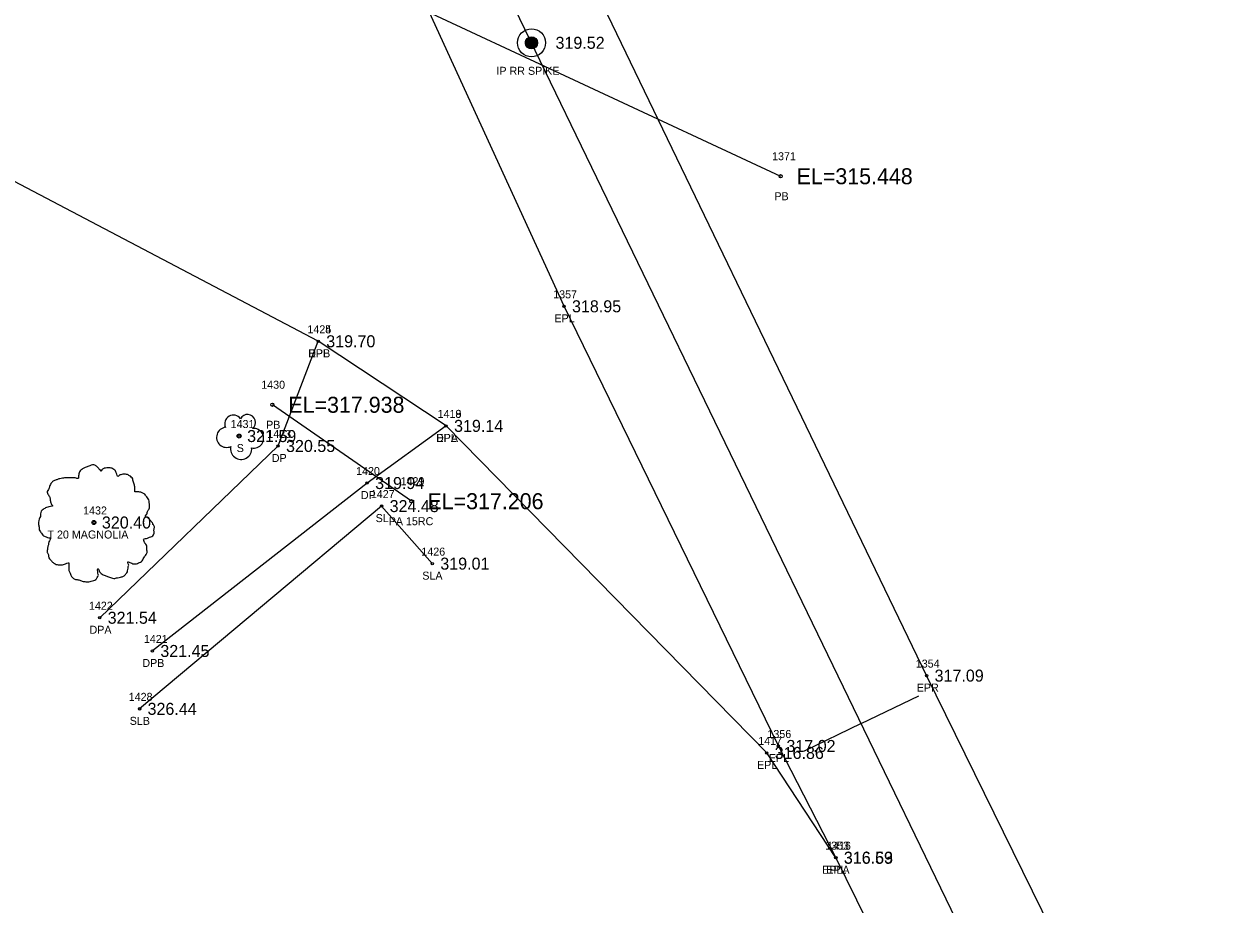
# Model space of a CAD drawing. Extents: x 1865045 to 1867370, y 910391 to 914218.
# Drawn here: x 1865995.4 to 1866144.3, y 911645.7 to 911755.7 of the extents above; entities that cross this region are included whole.
import ezdxf

# ---------------------------------------------------------------- set-up
doc = ezdxf.new("R2010")
doc.units = 0
for name, color, linetype in [('RD_EX_DR_Pipe', 7, 'Continuous'), ('RD_EX_DR_Pipe_txCode', 7, 'Continuous'), ('RD_EX_Driveway', 7, 'Continuous'), ('RD_EX_Driveway_txCode', 7, 'Continuous'), ('RD_EX_DV_Prop_txCode', 7, 'Continuous'), ('RD_EX_DV_PropPin', 7, 'Continuous'), ('RD_EX_Road', 7, 'Continuous'), ('RD_EX_Road_txCode', 7, 'Continuous'), ('RD_EX_TX_Driveway_ELEV', 7, 'Continuous'), ('RD_EX_TX_DV_Prop_ELEV', 7, 'Continuous'), ('RD_EX_TX_Road_ELEV', 7, 'Continuous'), ('RD_EX_TX_VEG_ELEV', 7, 'Continuous'), ('RD_EX_VEG', 7, 'Continuous'), ('RD_EX_VEG_txCode', 7, 'Continuous'), ('RD_HC_Cl', 7, 'Continuous'), ('RD_HC_Data_Tic', 7, 'Continuous'), ('RD_SMD_Locator', 7, 'Continuous'), ('RD_TX_Pipe_ElevEX', 7, 'Continuous')]:
    doc.layers.add(name, color=color, linetype=linetype)

msp = doc.modelspace()

# ---------------------------------------------------------------- linework, layer by layer
at = {"layer": 'RD_EX_DR_Pipe'}
for p, q in [((1866017.31, 911770.52), (1866089.93, 911736.64)), ((1866043.81, 911696.04), (1866026.44, 911708.09))]:
    msp.add_line(p, q, dxfattribs=at)
at = {"layer": 'RD_EX_Driveway'}
for points in [[(1866004.87, 911681.48), (1866027.15, 911702.94), (1866032.17, 911716.02)], [(1866048.14, 911705.45), (1866038.28, 911698.31), (1866011.45, 911677.33)]]:
    msp.add_lwpolyline(points, dxfattribs=at)
at = {"layer": 'RD_EX_DV_PropPin'}
for p, q in [((1866058.08, 911753.12), (1866058.08, 911753.51)), ((1866058.11, 911753.01), (1866058.11, 911753.61)), ((1866058.15, 911752.94), (1866058.15, 911753.68)), ((1866058.18, 911752.89), (1866058.18, 911753.74)), ((1866058.22, 911752.84), (1866058.22, 911753.79)), ((1866058.25, 911752.8), (1866058.25, 911753.83)), ((1866058.29, 911752.76), (1866058.29, 911753.86)), ((1866058.32, 911752.73), (1866058.32, 911753.89)), ((1866058.36, 911752.7), (1866058.36, 911753.92)), ((1866058.39, 911752.68), (1866058.39, 911753.95)), ((1866058.43, 911752.66), (1866058.43, 911753.97)), ((1866058.46, 911752.64), (1866058.46, 911753.99)), ((1866058.5, 911752.62), (1866058.5, 911754)), ((1866058.53, 911752.6), (1866058.53, 911754.02)), ((1866058.57, 911752.59), (1866058.57, 911754.03)), ((1866058.6, 911752.58), (1866058.6, 911754.04)), ((1866058.64, 911752.57), (1866058.64, 911754.05)), ((1866058.67, 911752.56), (1866058.67, 911754.06)), ((1866058.71, 911752.56), (1866058.71, 911754.07)), ((1866058.74, 911752.55), (1866058.74, 911754.07)), ((1866058.78, 911752.55), (1866058.78, 911754.07)), ((1866058.81, 911752.55), (1866058.81, 911754.07)), ((1866058.85, 911752.55), (1866058.85, 911754.07)), ((1866058.88, 911752.55), (1866058.88, 911754.07)), ((1866058.92, 911752.56), (1866058.92, 911754.07)), ((1866058.95, 911752.56), (1866058.95, 911754.06)), ((1866058.99, 911752.57), (1866058.99, 911754.05)), ((1866059.02, 911752.58), (1866059.02, 911754.04)), ((1866059.06, 911752.59), (1866059.06, 911754.03)), ((1866059.09, 911752.6), (1866059.09, 911754.02)), ((1866059.13, 911752.62), (1866059.13, 911754)), ((1866059.16, 911752.64), (1866059.16, 911753.99)), ((1866059.2, 911752.66), (1866059.2, 911753.97)), ((1866059.23, 911752.68), (1866059.23, 911753.95)), ((1866059.27, 911752.7), (1866059.27, 911753.92)), ((1866059.3, 911752.73), (1866059.3, 911753.89)), ((1866059.34, 911752.76), (1866059.34, 911753.86)), ((1866059.38, 911752.8), (1866059.38, 911753.83)), ((1866059.41, 911752.84), (1866059.41, 911753.79)), ((1866059.45, 911752.89), (1866059.45, 911753.74)), ((1866059.48, 911752.94), (1866059.48, 911753.68)), ((1866059.52, 911753.01), (1866059.52, 911753.61)), ((1866059.55, 911753.12), (1866059.55, 911753.51))]:
    msp.add_line(p, q, dxfattribs=at)
for radius in [1.75, 0.761]:
    msp.add_circle((1866058.81, 911753.31), radius, dxfattribs=at)
at = {"layer": 'RD_EX_Road'}
for points in [[(1866367.09, 911115.22), (1866376.17, 911119.76), (1866330.4, 911213.7), (1866286.92, 911304.16), (1866242.4, 911396.3), (1866197.74, 911488.67), (1866154.31, 911579.91), (1866143.08, 911603.17), (1866108.16, 911674.25), (1866059.64, 911774.84), (1866048.38, 911798.67), (1866045.99, 911803.62)], [(1866367.09, 911115.22), (1866357.99, 911110.97), (1866313.12, 911203.44), (1866268.86, 911295.9), (1866224.24, 911388.66), (1866179.87, 911480.6), (1866149.84, 911543.41), (1866142.18, 911559.37), (1866135.93, 911572.05), (1866096.83, 911651.51), (1866089.65, 911665.46), (1866062.87, 911720.39), (1866042.14, 911765.69), (1866027.93, 911795.04)], [(1866096.82, 911651.49), (1866088.19, 911664.59), (1866048.14, 911705.45), (1866032.17, 911716.02), (1865982.01, 911742.39)]]:
    msp.add_lwpolyline(points, dxfattribs=at)
at = {"layer": 'RD_EX_VEG'}
msp.add_lwpolyline([(1866046.42, 911688.24), (1866040.09, 911695.43), (1866009.85, 911670.1)], dxfattribs=at)
for centre, radius in [((1866022.29, 911704.18), 0.25), ((1866004.15, 911693.38), 0.25), ((1866004.14, 911693.36), 0.0001)]:
    msp.add_circle(centre, radius, dxfattribs=at)
for centre, radius, start, end in [((1866021.57, 911705.72), 1.08, 34.9763, 204.756), ((1866023.34, 911705.88), 0.995, 308.7626, 152.0467), ((1866020.73, 911704.02), 1.26, 96.4518, 294.734), ((1866024.13, 911703.9), 1.22, 256.5667, 98.1046), ((1866022.54, 911702.58), 1.32, 166.8827, 5.7589)]:
    msp.add_arc(centre, radius, start, end, dxfattribs=at)
for points in [[(1866004.28, 911700.55), (1866003.98, 911700.57), (1866003.66, 911700.47), (1866003.41, 911700.37), (1866003.18, 911700.3), (1866002.96, 911700.2), (1866002.66, 911700.02), (1866002.43, 911699.82), (1866002.31, 911699.57), (1866002.26, 911699.35), (1866002.21, 911699.07), (1866002.21, 911698.9), (1866002.08, 911698.87), (1866001.93, 911698.9), (1866001.68, 911698.97), (1866001.43, 911698.97), (1866001.18, 911698.97), (1866000.83, 911698.95), (1866000.48, 911698.95), (1866000.21, 911698.9), (1865999.88, 911698.85), (1865999.51, 911698.72), (1865999.16, 911698.6), (1865998.86, 911698.35), (1865998.61, 911697.87), (1865998.48, 911697.52), (1865998.33, 911697.27), (1865998.48, 911696.82), (1865998.66, 911696.47), (1865998.68, 911696.27), (1865998.76, 911695.85), (1865998.86, 911695.62), (1865998.98, 911695.42), (1865998.91, 911695.4), (1865998.53, 911695.35), (1865998.23, 911695.25), (1865997.81, 911695.02), (1865997.58, 911694.8), (1865997.48, 911694.47), (1865997.46, 911694.12), (1865997.36, 911693.93), (1865997.28, 911693.65), (1865997.26, 911693.58), (1865997.21, 911693.25), (1865997.31, 911692.8), (1865997.33, 911692.45), (1865997.46, 911692.23), (1865997.61, 911692.05), (1865997.78, 911691.8), (1865998.18, 911691.58), (1865998.51, 911691.48), (1865998.71, 911691.45), (1865998.53, 911690.95), (1865998.48, 911690.6), (1865998.36, 911690.2), (1865998.36, 911690.13), (1865998.31, 911689.65), (1865998.46, 911689.33), (1865998.53, 911688.95), (1865998.71, 911688.73), (1865998.98, 911688.43), (1865999.31, 911688.2), (1865999.81, 911688.08), (1866000.21, 911688.1), (1866000.78, 911688.28), (1866001.03, 911688.35), (1866001.01, 911688.18), (1866001.03, 911687.8), (1866001.03, 911687.38), (1866001.18, 911687.05), (1866001.28, 911686.78), (1866001.43, 911686.53), (1866001.76, 911686.3), (1866002.16, 911686.23), (1866002.58, 911686.08), (1866003.03, 911686), (1866003.53, 911685.98), (1866004.13, 911686.13), (1866004.41, 911686.25), (1866004.51, 911686.43), (1866004.71, 911686.8), (1866004.66, 911687.03), (1866004.68, 911687.63), (1866004.78, 911687.45), (1866004.96, 911687.1), (1866005.45, 911686.8), (1866005.85, 911686.63), (1866006.33, 911686.48), (1866006.63, 911686.4), (1866007.1, 911686.48), (1866007.48, 911686.55), (1866007.85, 911686.68), (1866008.15, 911686.95), (1866008.33, 911687.23), (1866008.38, 911687.5), (1866008.45, 911687.88), (1866008.5, 911688.05)], [(1866008.5, 911688.05), (1866008.43, 911688.23), (1866008.38, 911688.48), (1866008.45, 911688.45), (1866008.63, 911688.4), (1866008.9, 911688.28), (1866009.13, 911688.2), (1866009.45, 911688.23), (1866009.73, 911688.33), (1866010.18, 911688.6), (1866010.45, 911689.08), (1866010.73, 911689.48), (1866010.8, 911689.8), (1866010.75, 911690.03), (1866010.73, 911690.53), (1866010.53, 911690.78), (1866010.48, 911690.9), (1866010.38, 911691.3), (1866010.45, 911691.35), (1866010.73, 911691.4), (1866011.1, 911691.53), (1866011.38, 911691.65), (1866011.6, 911691.83), (1866011.68, 911692.05), (1866011.65, 911692.45), (1866011.7, 911692.85), (1866011.63, 911693), (1866011.53, 911693.15), (1866011.45, 911693.35), (1866011.3, 911693.5), (1866011.2, 911693.65), (1866011.1, 911693.75), (1866010.98, 911693.9), (1866010.8, 911694.02), (1866010.65, 911694.07), (1866010.6, 911694.22), (1866010.75, 911694.42), (1866010.8, 911694.52), (1866010.83, 911694.75), (1866011.05, 911695.1), (1866011.1, 911695.5), (1866011.05, 911695.92), (1866011, 911696.2), (1866010.85, 911696.47), (1866010.65, 911696.72), (1866010.53, 911696.9), (1866010.35, 911697.02), (1866010.03, 911697.15), (1866009.78, 911697.2), (1866009.43, 911697.2), (1866009.23, 911697.25), (1866009.25, 911697.3), (1866009.25, 911697.45), (1866009.25, 911697.72), (1866009.18, 911698.17), (1866009.03, 911698.67), (1866009.03, 911698.7), (1866008.93, 911698.95), (1866008.7, 911699.15), (1866008.53, 911699.25), (1866008.33, 911699.37), (1866008.08, 911699.4), (1866007.78, 911699.4), (1866007.5, 911699.35), (1866007.3, 911699.25), (1866007.13, 911699.12), (1866007.05, 911699.27), (1866006.95, 911699.57), (1866006.9, 911699.72), (1866006.75, 911699.9), (1866006.53, 911700.1), (1866006.08, 911700.22), (1866005.45, 911700.15), (1866005.16, 911699.95), (1866005.01, 911699.77), (1866004.96, 911699.9), (1866004.76, 911700.1), (1866004.66, 911700.27), (1866004.48, 911700.4), (1866004.33, 911700.5), (1866004.23, 911700.55)]]:
    msp.add_spline(points, degree=3, dxfattribs=at)
at = {"layer": 'RD_HC_Cl'}
msp.add_line((1866280.52, 911295.32), (1866034.98, 911802.56), dxfattribs=at)
at = {"layer": 'RD_HC_Data_Tic'}
for q in [(1866107.19, 911671.73), (1866092.79, 911664.76)]:
    msp.add_line((1866099.99, 911668.25), q, dxfattribs=at)
at = {"layer": 'RD_SMD_Locator'}
for centre, radius in [((1866058.81, 911753.31), 0.15), ((1866089.93, 911736.64), 0.2), ((1866062.87, 911720.39), 0.15), ((1866032.17, 911716.02), 0.15), ((1866032.17, 911716.02), 0.15), ((1866026.44, 911708.09), 0.2), ((1866048.14, 911705.45), 0.15), ((1866048.14, 911705.45), 0.15), ((1866022.29, 911704.18), 0.15), ((1866027.15, 911702.94), 0.15), ((1866038.28, 911698.31), 0.15), ((1866043.81, 911696.04), 0.2), ((1866040.09, 911695.43), 0.15), ((1866004.15, 911693.38), 0.15), ((1866046.42, 911688.24), 0.15), ((1866004.87, 911681.48), 0.15), ((1866011.45, 911677.33), 0.15), ((1866108.16, 911674.25), 0.15), ((1866009.85, 911670.1), 0.15), ((1866089.65, 911665.46), 0.15), ((1866088.19, 911664.59), 0.15), ((1866096.82, 911651.49), 0.15), ((1866096.83, 911651.51), 0.15)]:
    msp.add_circle(centre, radius, dxfattribs=at)

# ---------------------------------------------------------------- texts
at = {"layer": 'RD_EX_DR_Pipe_txCode'}
for s, p in [('1371', (1866088.86, 911738.64)), ('PB', (1866089.15, 911733.64)), ('1430', (1866025.05, 911710.09)), ('PB', (1866025.66, 911705.09)), ('1429', (1866042.46, 911698.04)), ('PA 15RC', (1866040.97, 911693.04))]:
    msp.add_text(s, height=1, dxfattribs=at).set_placement(p)
at = {"layer": 'RD_EX_Driveway_txCode'}
for s, p in [('1424', (1866030.82, 911717.02)), ('DPB', (1866030.92, 911714.02)), ('1419', (1866047.08, 911706.45)), ('1423', (1866025.81, 911703.94)), ('DPA', (1866046.88, 911703.45)), ('DP', (1866026.37, 911700.94)), ('1420', (1866036.9, 911699.31)), ('DP', (1866037.5, 911696.31)), ('1422', (1866003.53, 911682.48)), ('DPA', (1866003.6, 911679.48)), ('1421', (1866010.39, 911678.33)), ('DPB', (1866010.2, 911675.33))]:
    msp.add_text(s, height=1, dxfattribs=at).set_placement(p)
at = {"layer": 'RD_EX_DV_Prop_txCode'}
msp.add_text('IP RR SPIKE', height=1, dxfattribs=at).set_placement((1866054.43, 911749.31))
at = {"layer": 'RD_EX_Road_txCode'}
for s, p in [('1357', (1866061.52, 911721.39)), ('EPL', (1866061.67, 911718.39)), ('1425', (1866030.82, 911717.02)), ('EPL', (1866030.96, 911714.02)), ('1418', (1866047.08, 911706.45)), ('EPL', (1866046.94, 911703.45)), ('1354', (1866106.81, 911675.25)), ('EPR', (1866106.93, 911672.25)), ('1417', (1866087.13, 911665.59)), ('1356', (1866088.28, 911666.46)), ('EPL', (1866086.98, 911662.59)), ('EPL', (1866088.45, 911663.46)), ('1353', (1866095.49, 911652.51)), ('1416', (1866095.73, 911652.49)), ('EPLA', (1866095.12, 911649.49)), ('EPL', (1866095.63, 911649.51))]:
    msp.add_text(s, height=1, dxfattribs=at).set_placement(p)
at = {"layer": 'RD_EX_TX_Driveway_ELEV'}
for s, p in [('319.70', (1866033.17, 911715.27)), ('319.14', (1866049.14, 911704.7)), ('320.55', (1866028.15, 911702.19)), ('319.94', (1866039.28, 911697.56)), ('321.54', (1866005.87, 911680.73)), ('321.45', (1866012.45, 911676.58))]:
    msp.add_text(s, height=1.5, dxfattribs=at).set_placement(p)
at = {"layer": 'RD_EX_TX_DV_Prop_ELEV'}
msp.add_text('319.52', height=1.5, dxfattribs=at).set_placement((1866061.81, 911752.56))
at = {"layer": 'RD_EX_TX_Road_ELEV'}
for s, p in [('318.95', (1866063.87, 911719.64)), ('319.70', (1866033.17, 911715.27)), ('319.14', (1866049.14, 911704.7)), ('317.09', (1866109.16, 911673.5)), ('316.86', (1866089.19, 911663.84)), ('317.02', (1866090.65, 911664.71)), ('316.59', (1866097.82, 911650.74)), ('316.63', (1866097.83, 911650.76))]:
    msp.add_text(s, height=1.5, dxfattribs=at).set_placement(p)
at = {"layer": 'RD_EX_TX_VEG_ELEV'}
for s, p in [('321.59', (1866023.29, 911703.43)), ('324.48', (1866041.09, 911694.68)), ('320.40', (1866005.15, 911692.63)), ('319.01', (1866047.42, 911687.49)), ('326.44', (1866010.85, 911669.35))]:
    msp.add_text(s, height=1.5, dxfattribs=at).set_placement(p)
at = {"layer": 'RD_EX_VEG_txCode'}
for s, p in [('1431', (1866021.23, 911705.18)), ('S', (1866021.99, 911702.18)), ('1427', (1866038.74, 911696.43)), ('1432', (1866002.8, 911694.38)), ('SL', (1866039.34, 911693.43)), ('T 20 MAGNOLIA', (1865998.35, 911691.38)), ('1426', (1866045.05, 911689.24)), ('SLA', (1866045.17, 911686.24)), ('1428', (1866008.5, 911671.1)), ('SLB', (1866008.62, 911668.1))]:
    msp.add_text(s, height=1, dxfattribs=at).set_placement(p)
at = {"layer": 'RD_TX_Pipe_ElevEX'}
for s, p in [('EL=315.448', (1866091.93, 911735.64)), ('EL=317.938', (1866028.44, 911707.09)), ('EL=317.206', (1866045.81, 911695.04))]:
    msp.add_text(s, height=2, dxfattribs=at).set_placement(p)

doc.saveas('drawing.dxf')
